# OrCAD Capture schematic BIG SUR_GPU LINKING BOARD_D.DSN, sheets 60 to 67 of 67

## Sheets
60 P62  P1V8 VR for PLX-1: size B
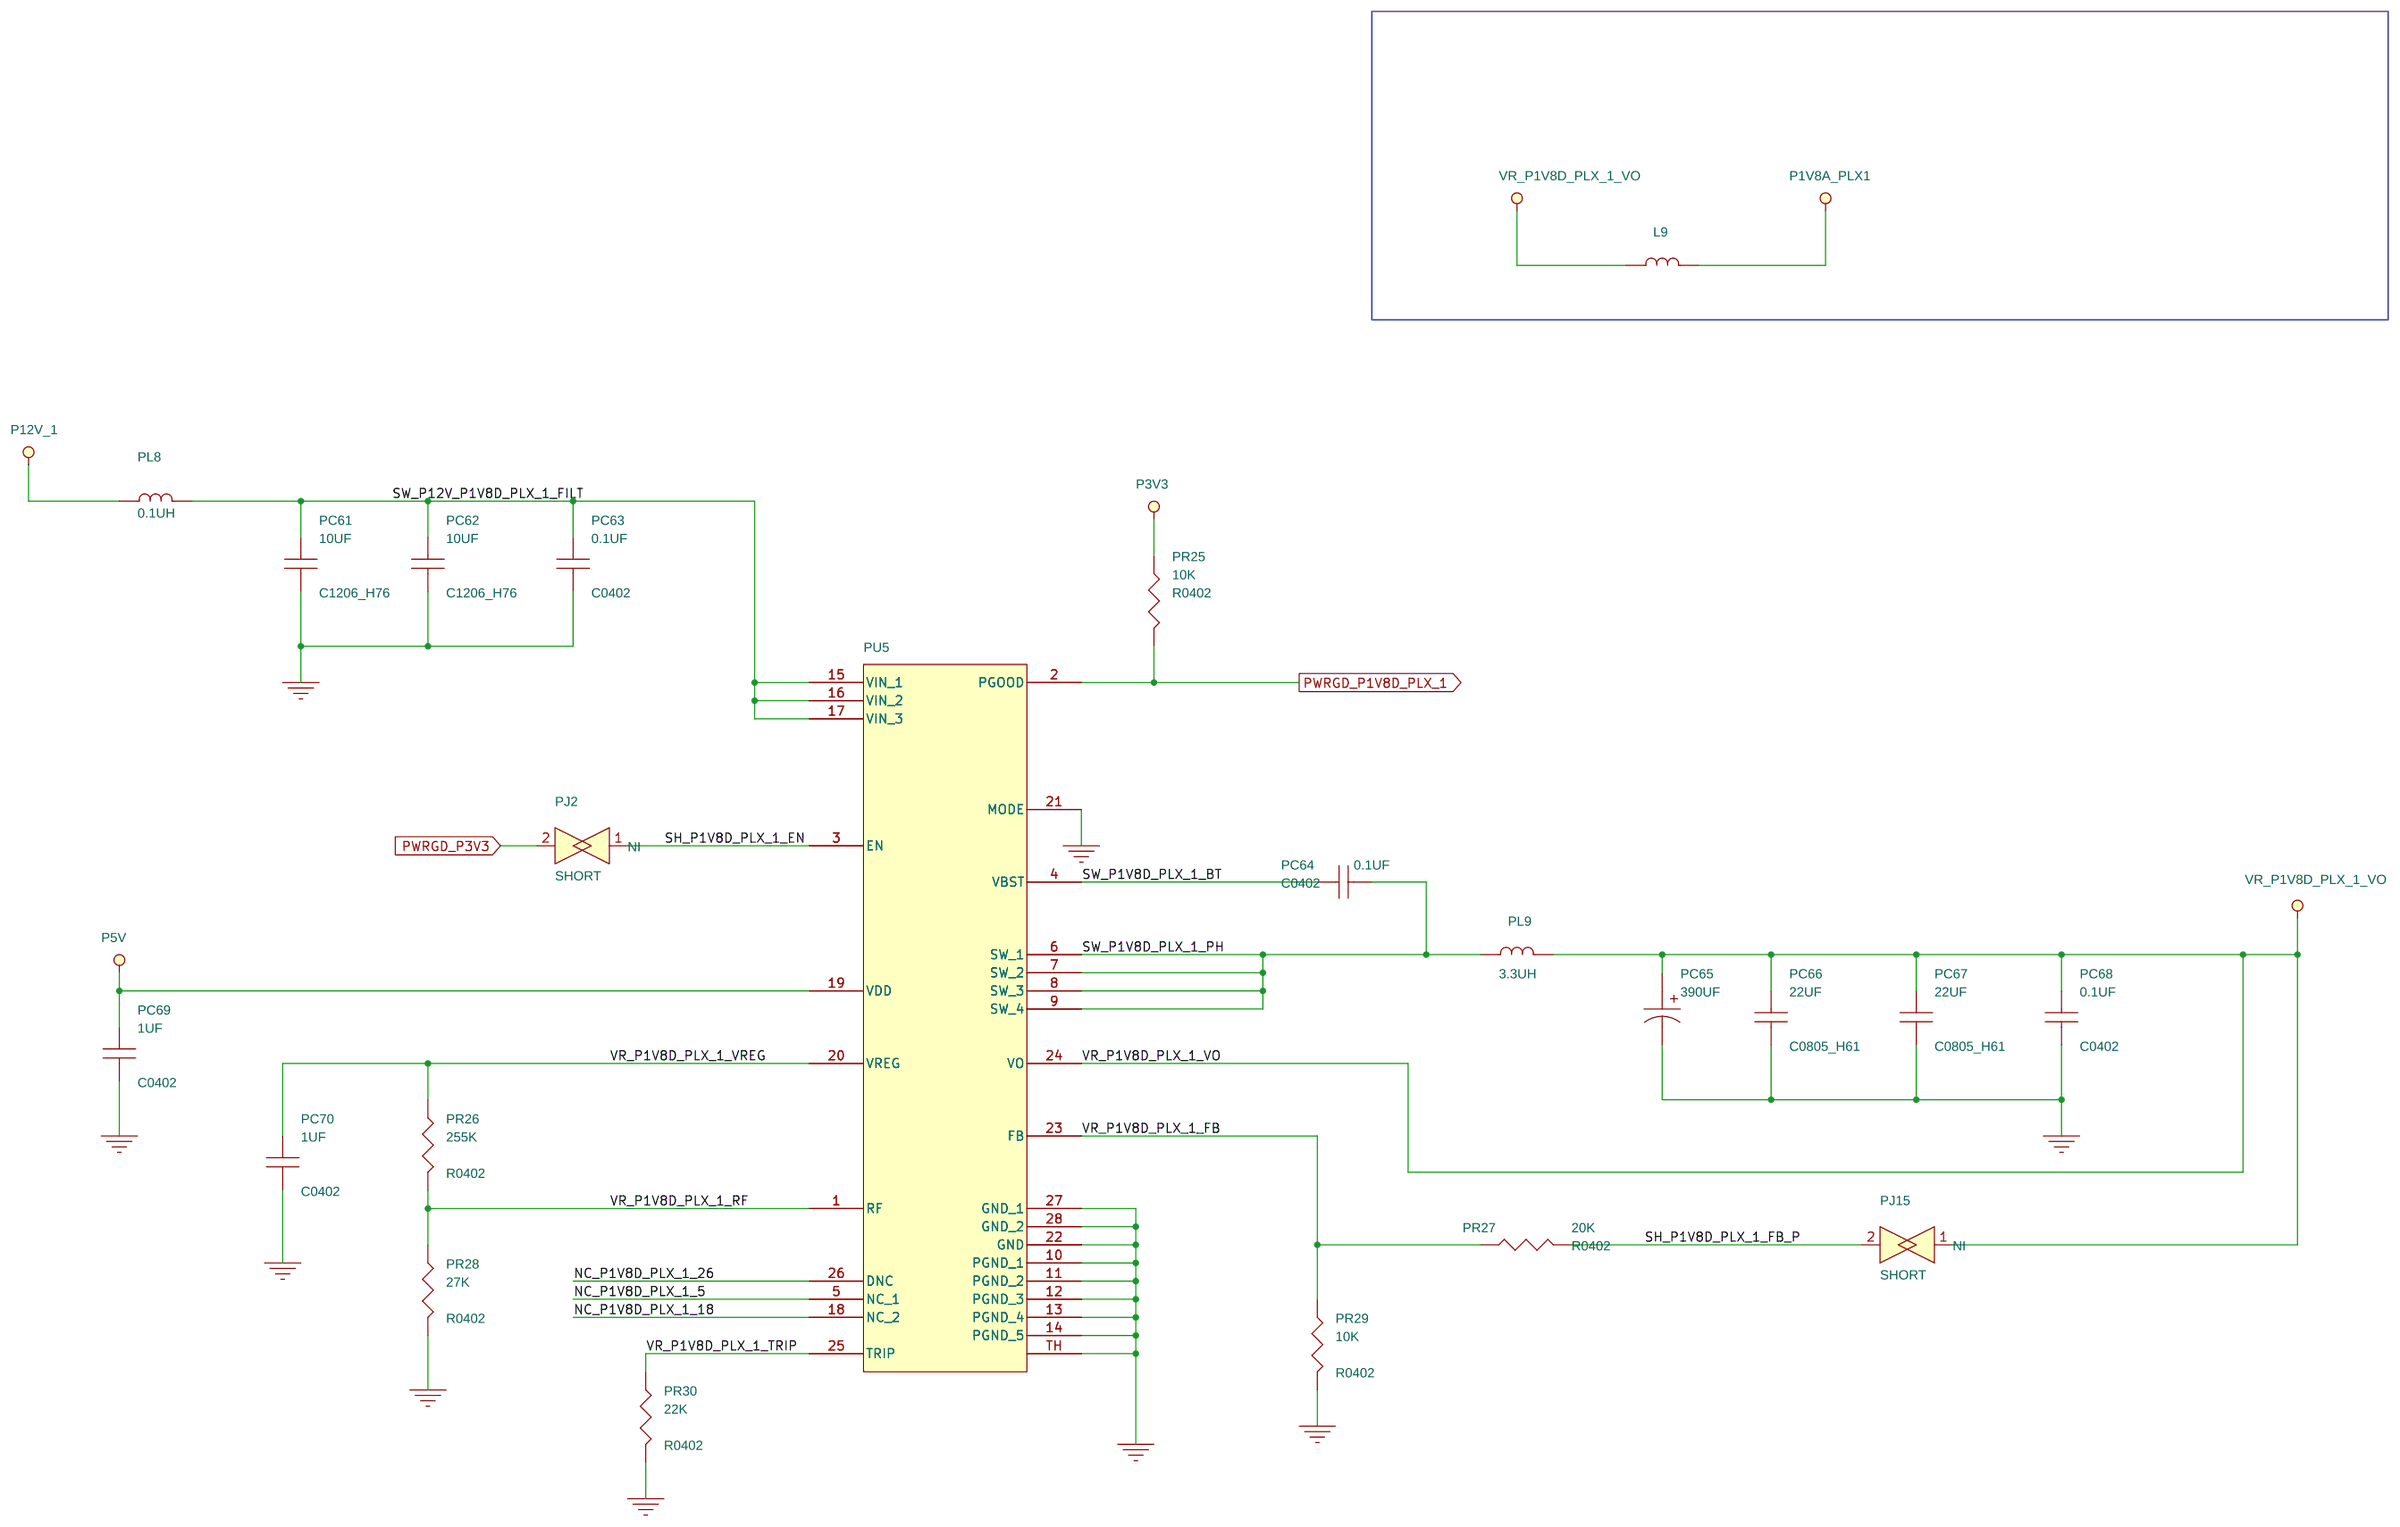
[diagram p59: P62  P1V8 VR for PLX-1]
61 P63  P1V8 VR for PLX-2: size B
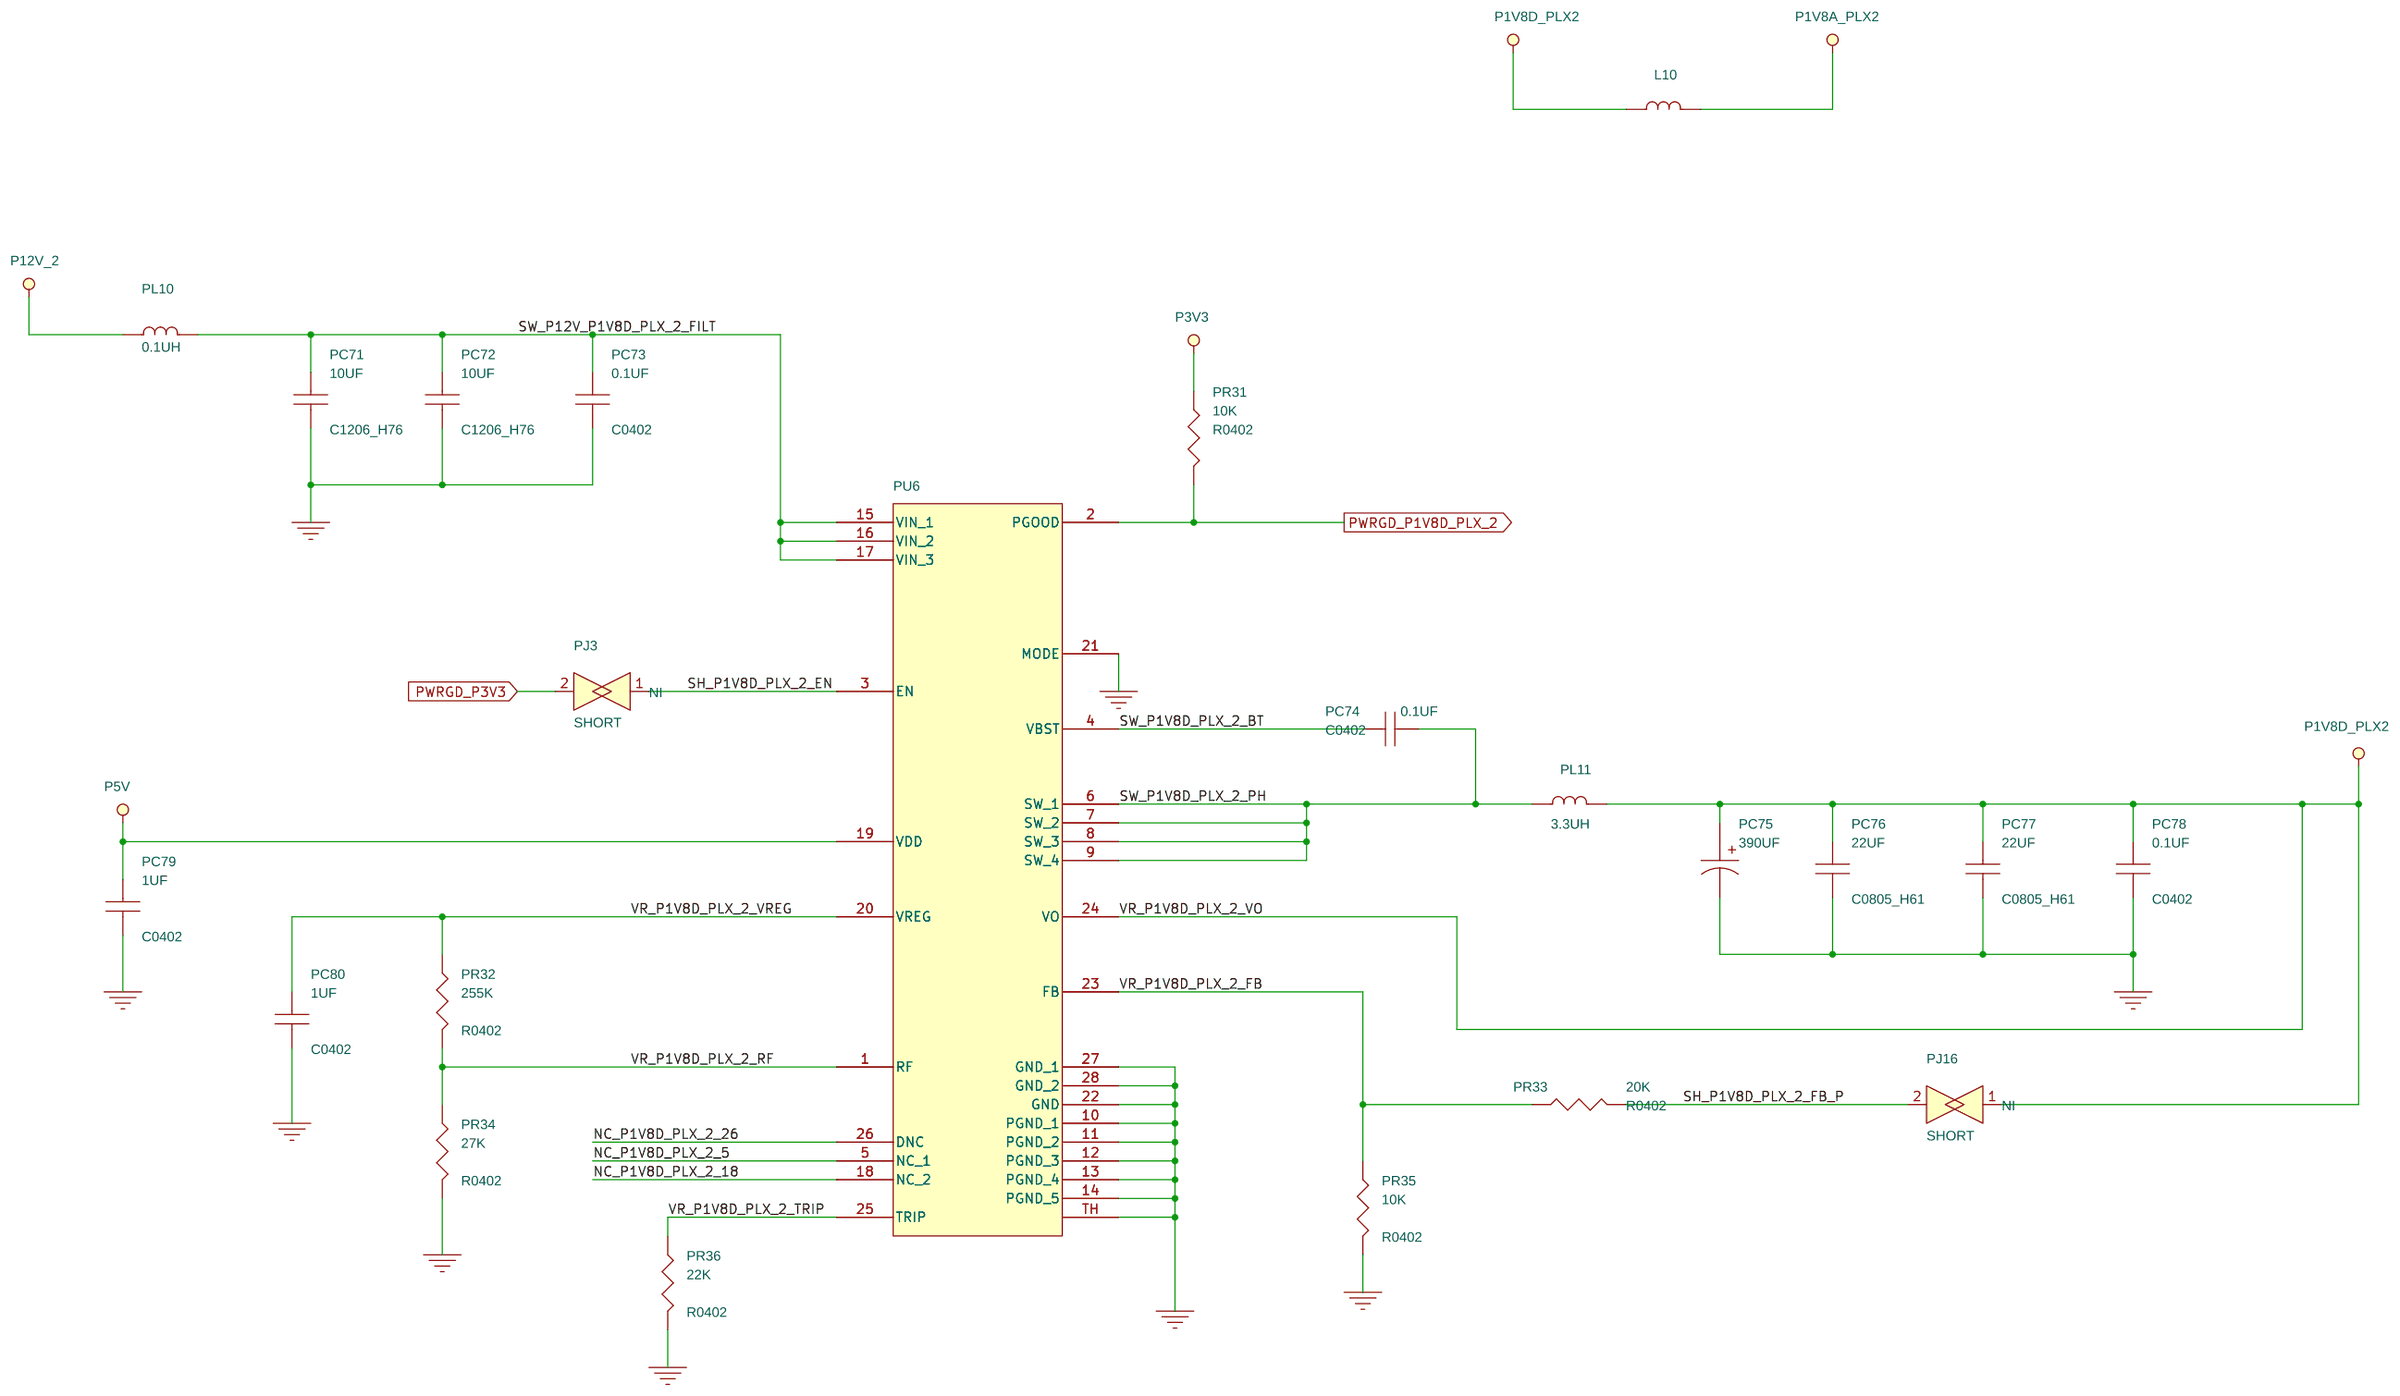
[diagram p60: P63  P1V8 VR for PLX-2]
62 P64  P0V9D VR for PLX-1: size A3
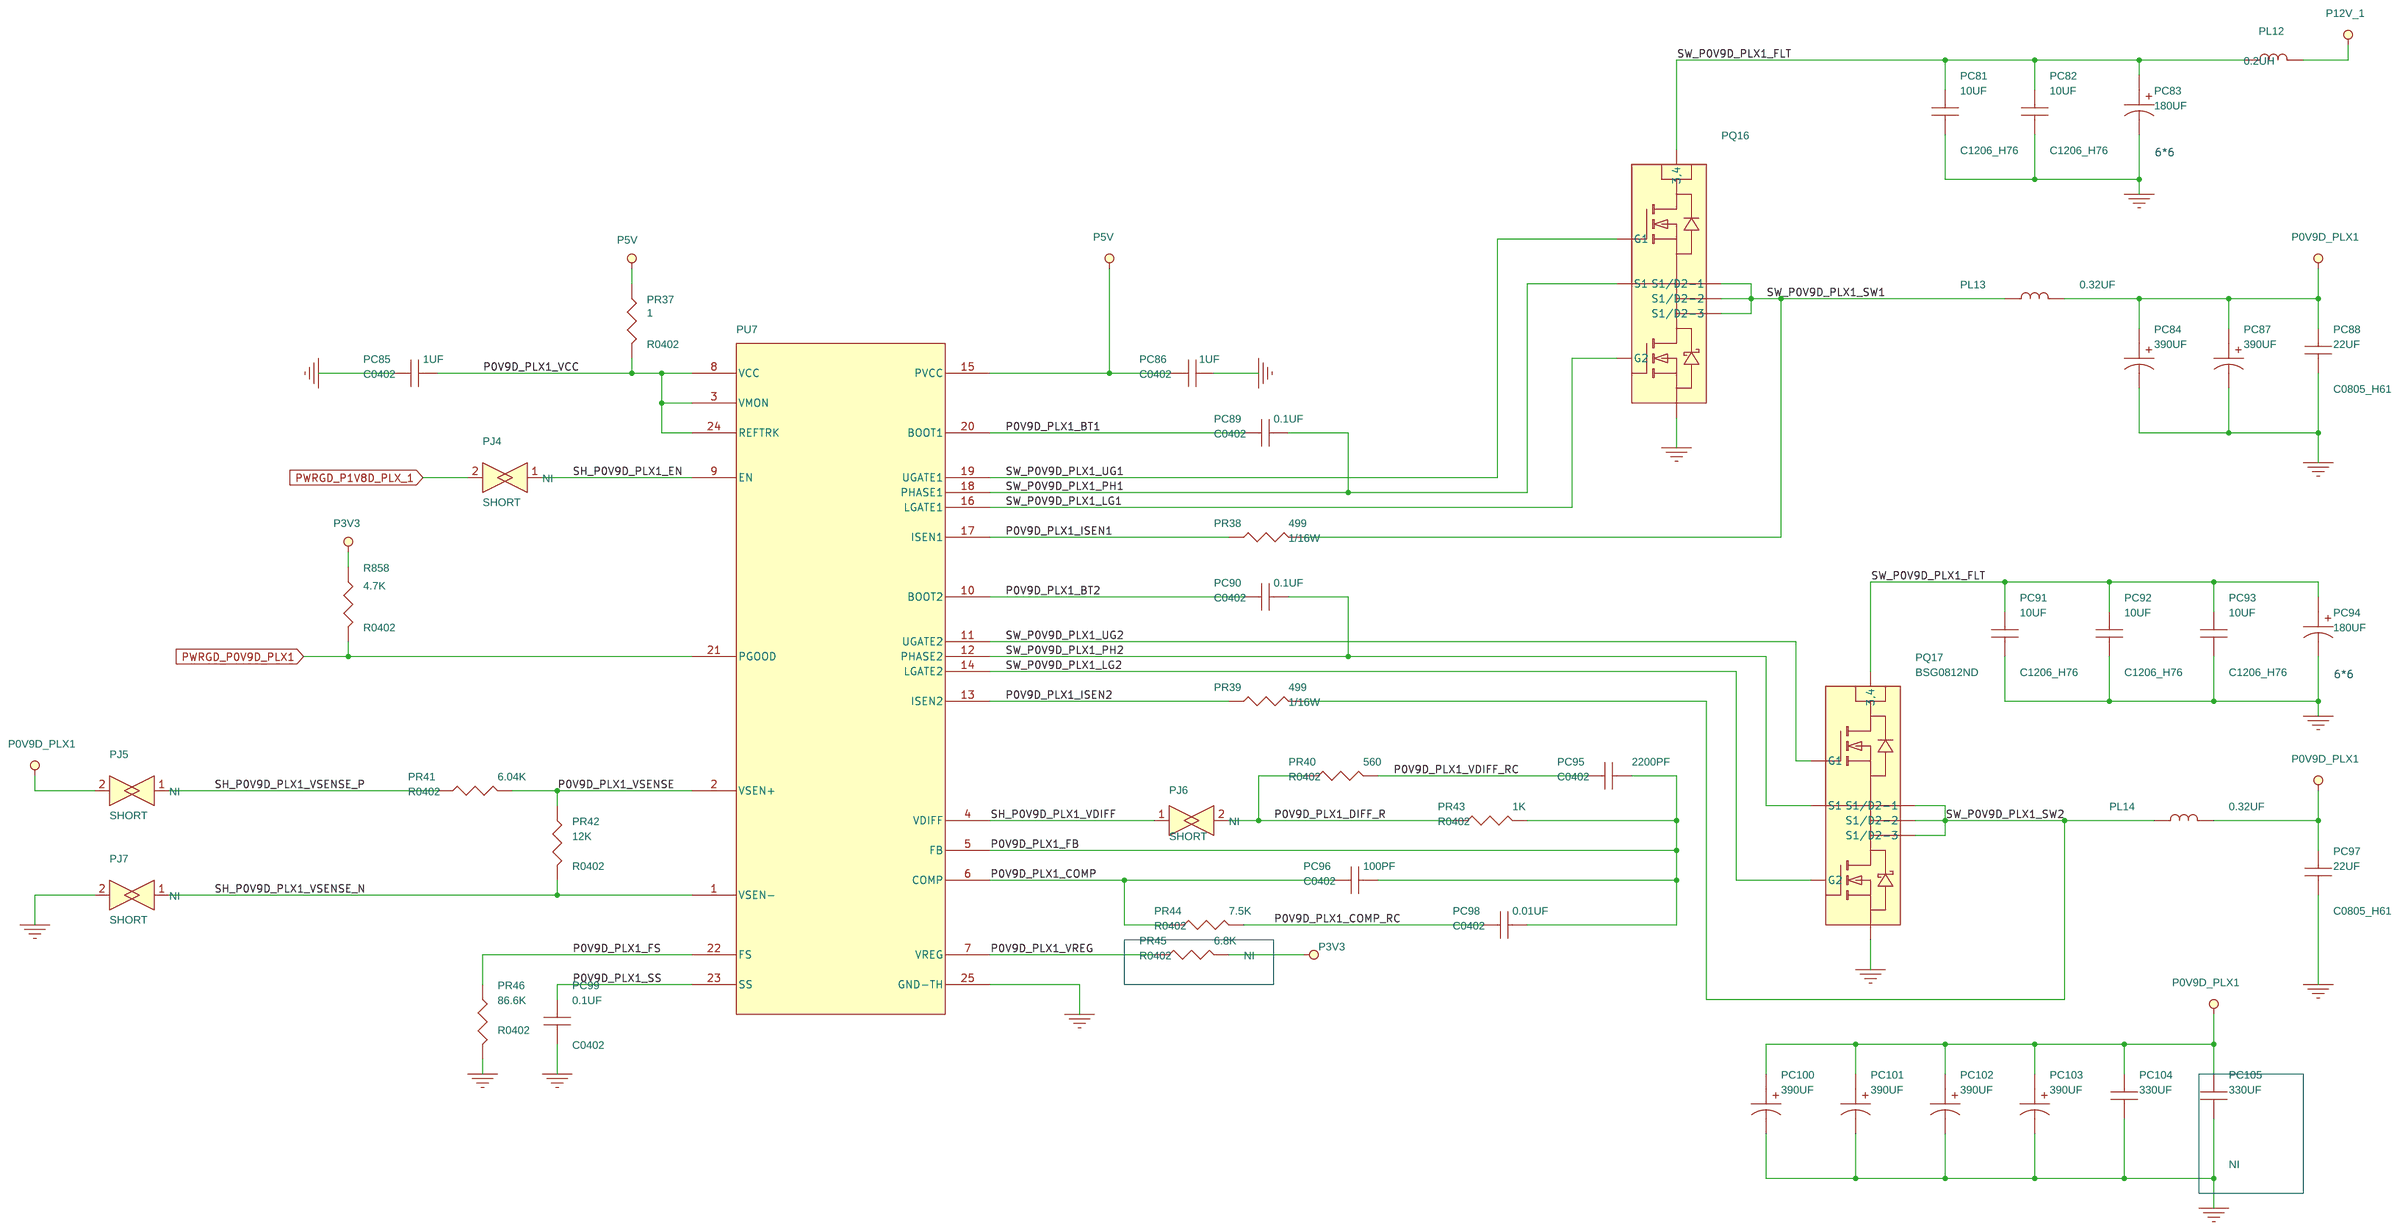
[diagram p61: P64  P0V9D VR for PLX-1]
63 P65  P0V9D VR for PLX-2: size A3
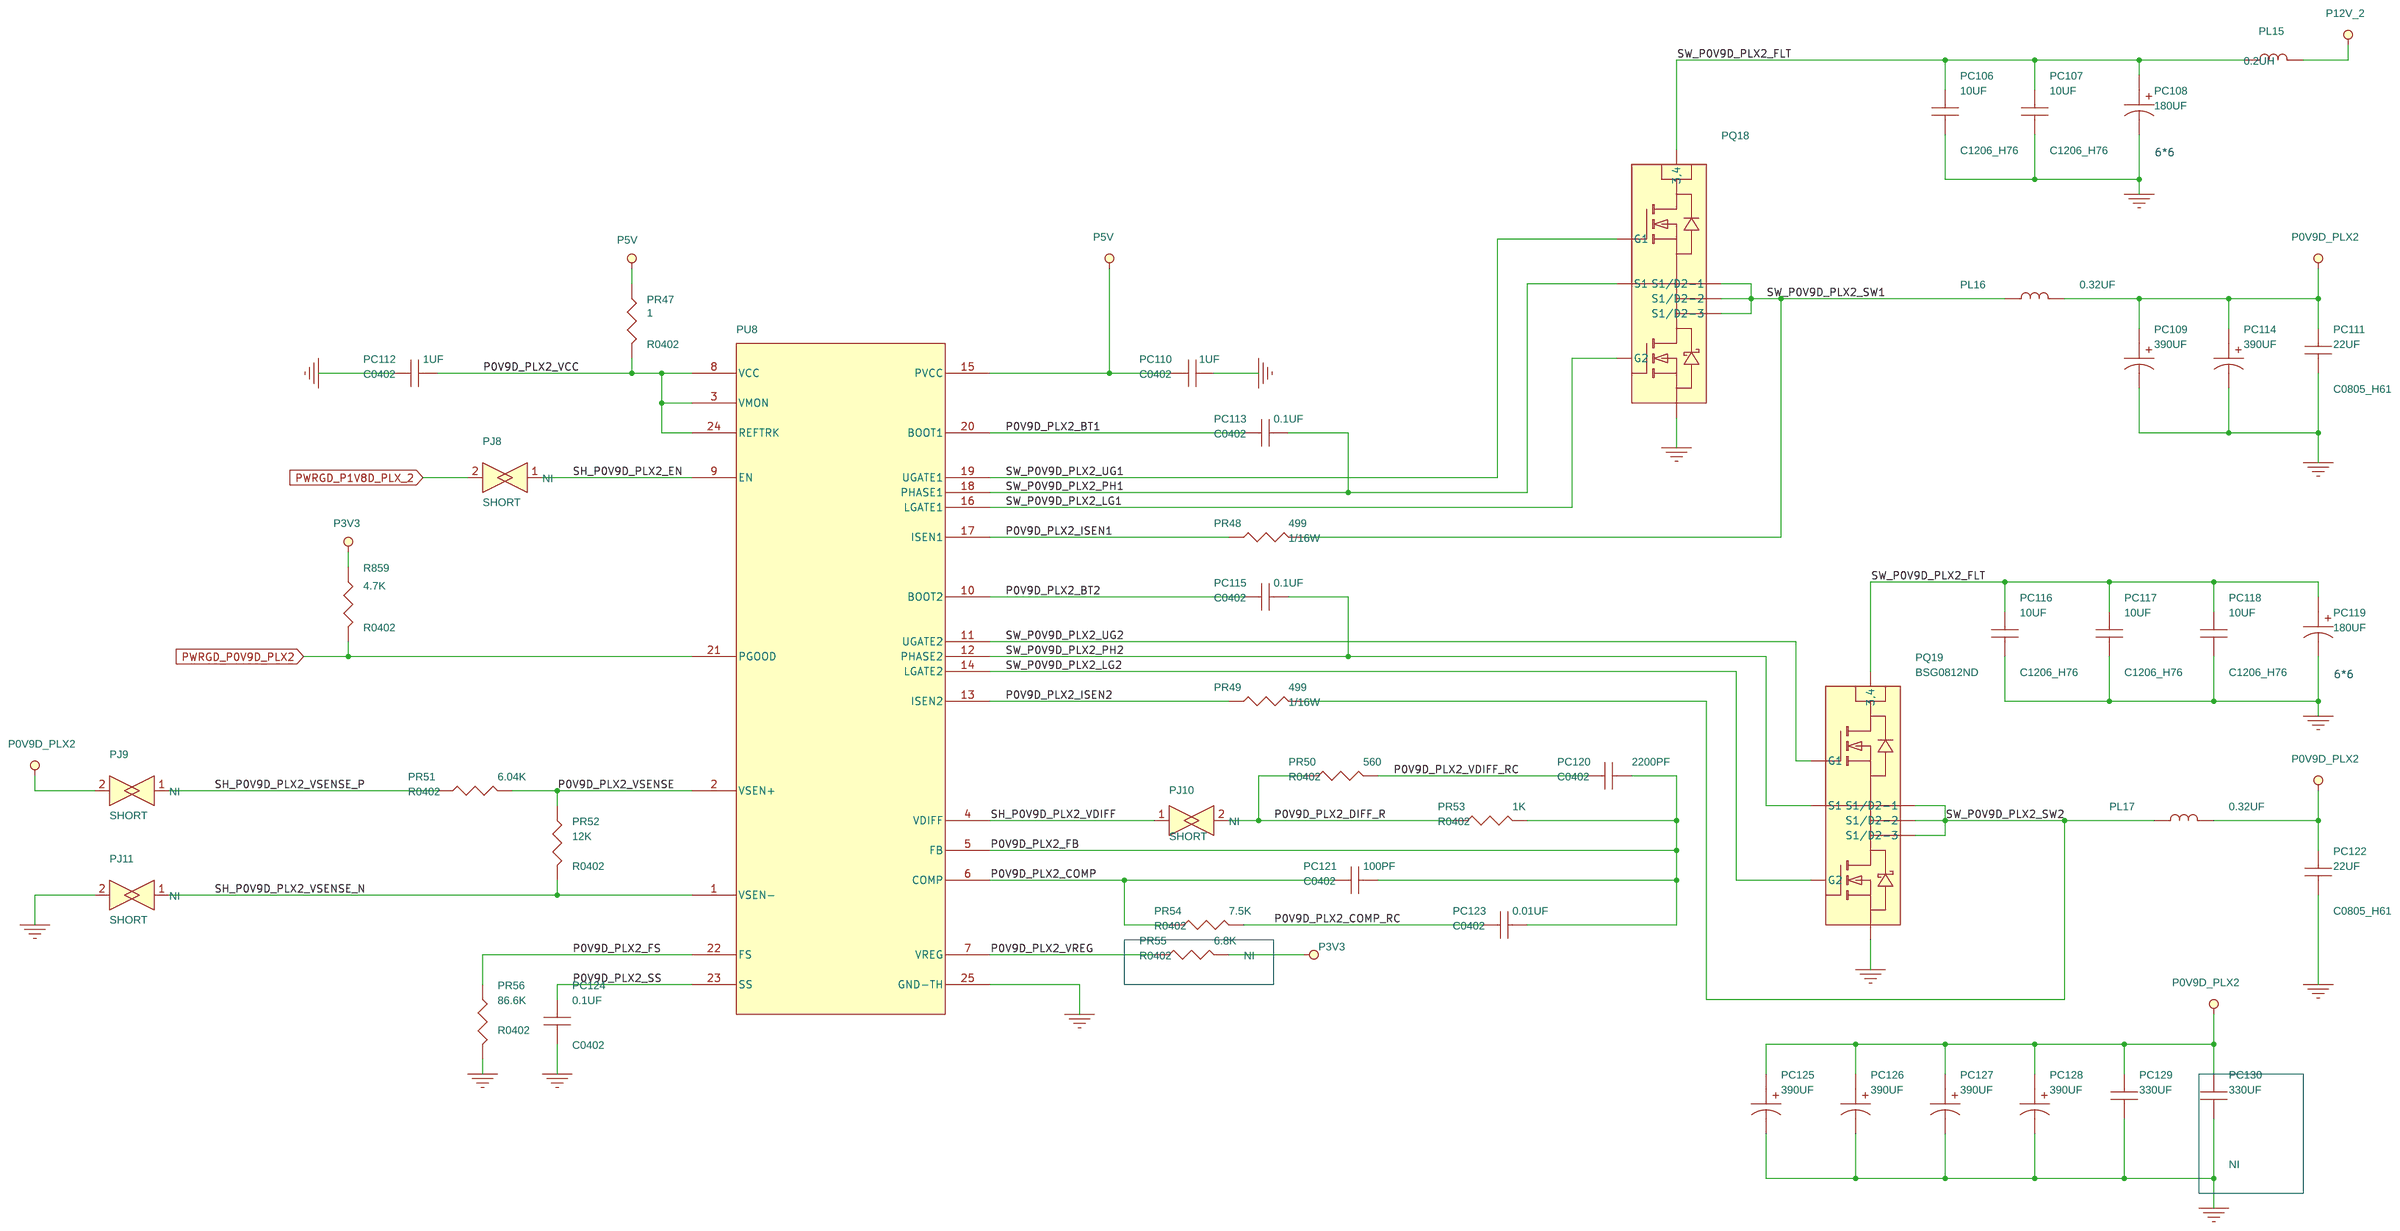
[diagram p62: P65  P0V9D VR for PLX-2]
64 P66  P0V9A VR for PLX-1: size A3
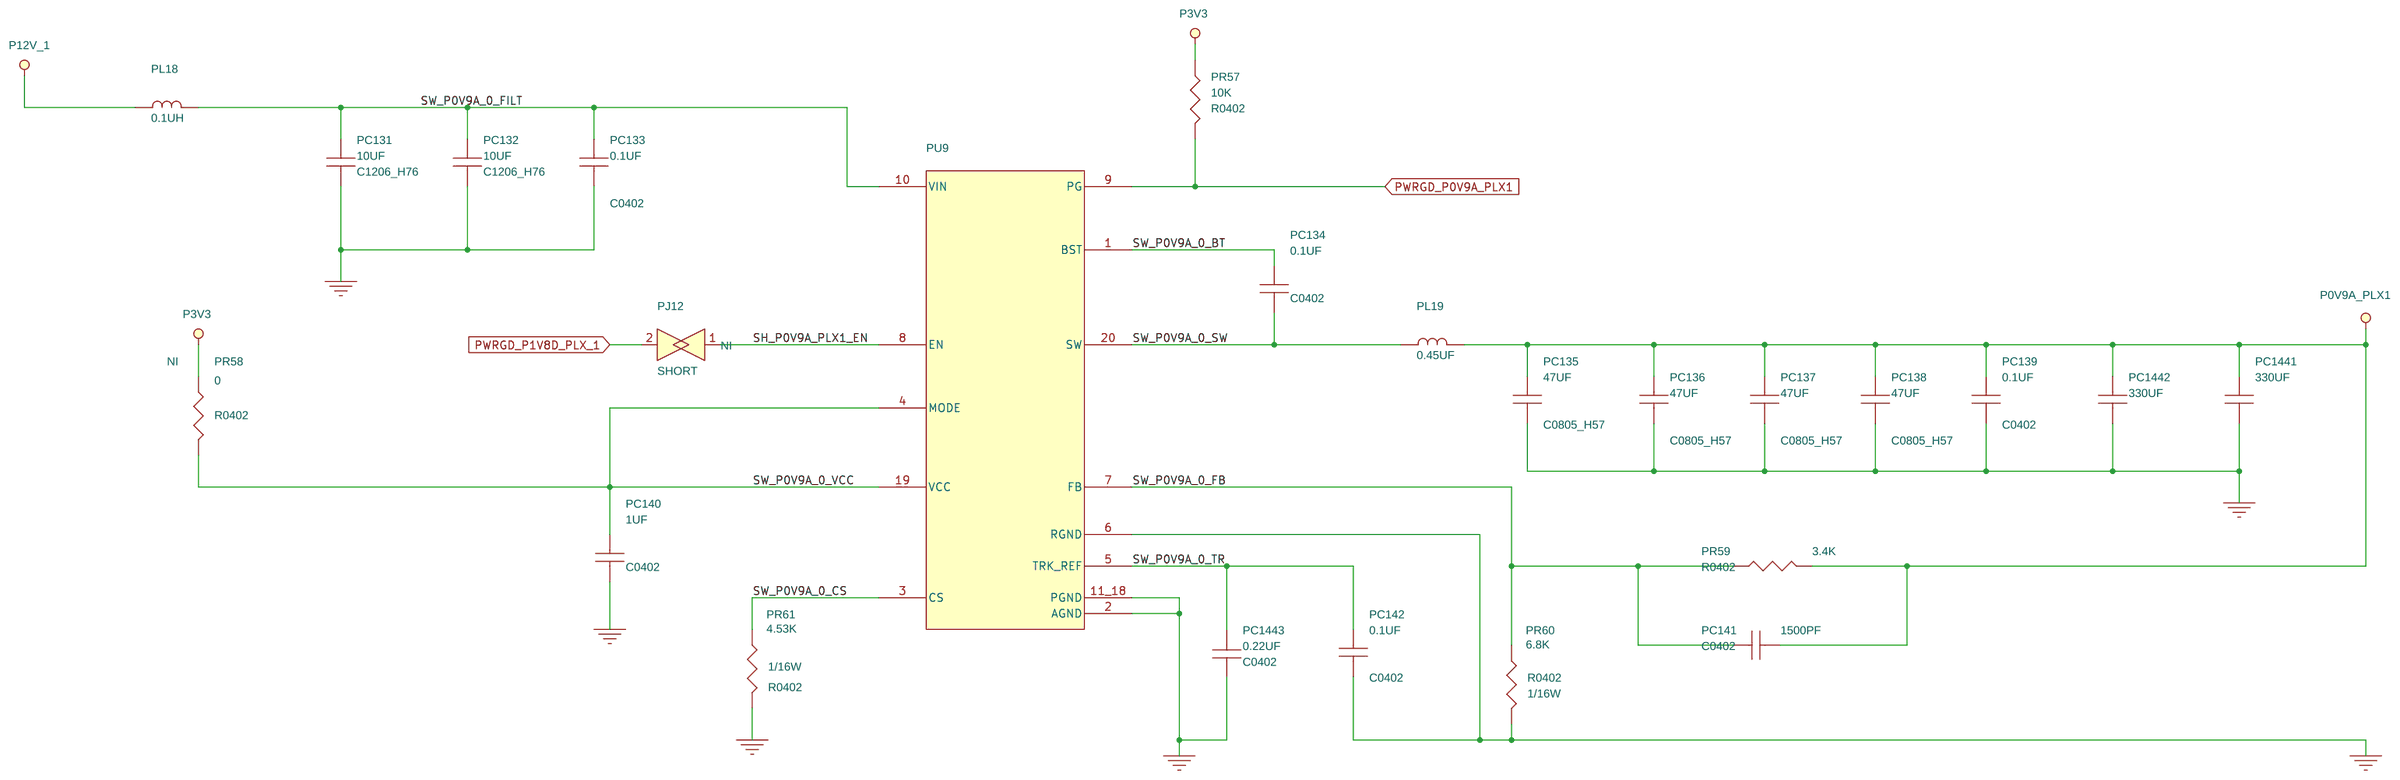
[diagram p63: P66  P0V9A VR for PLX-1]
65 P67  P0V9A VR for PLX-2: size A3
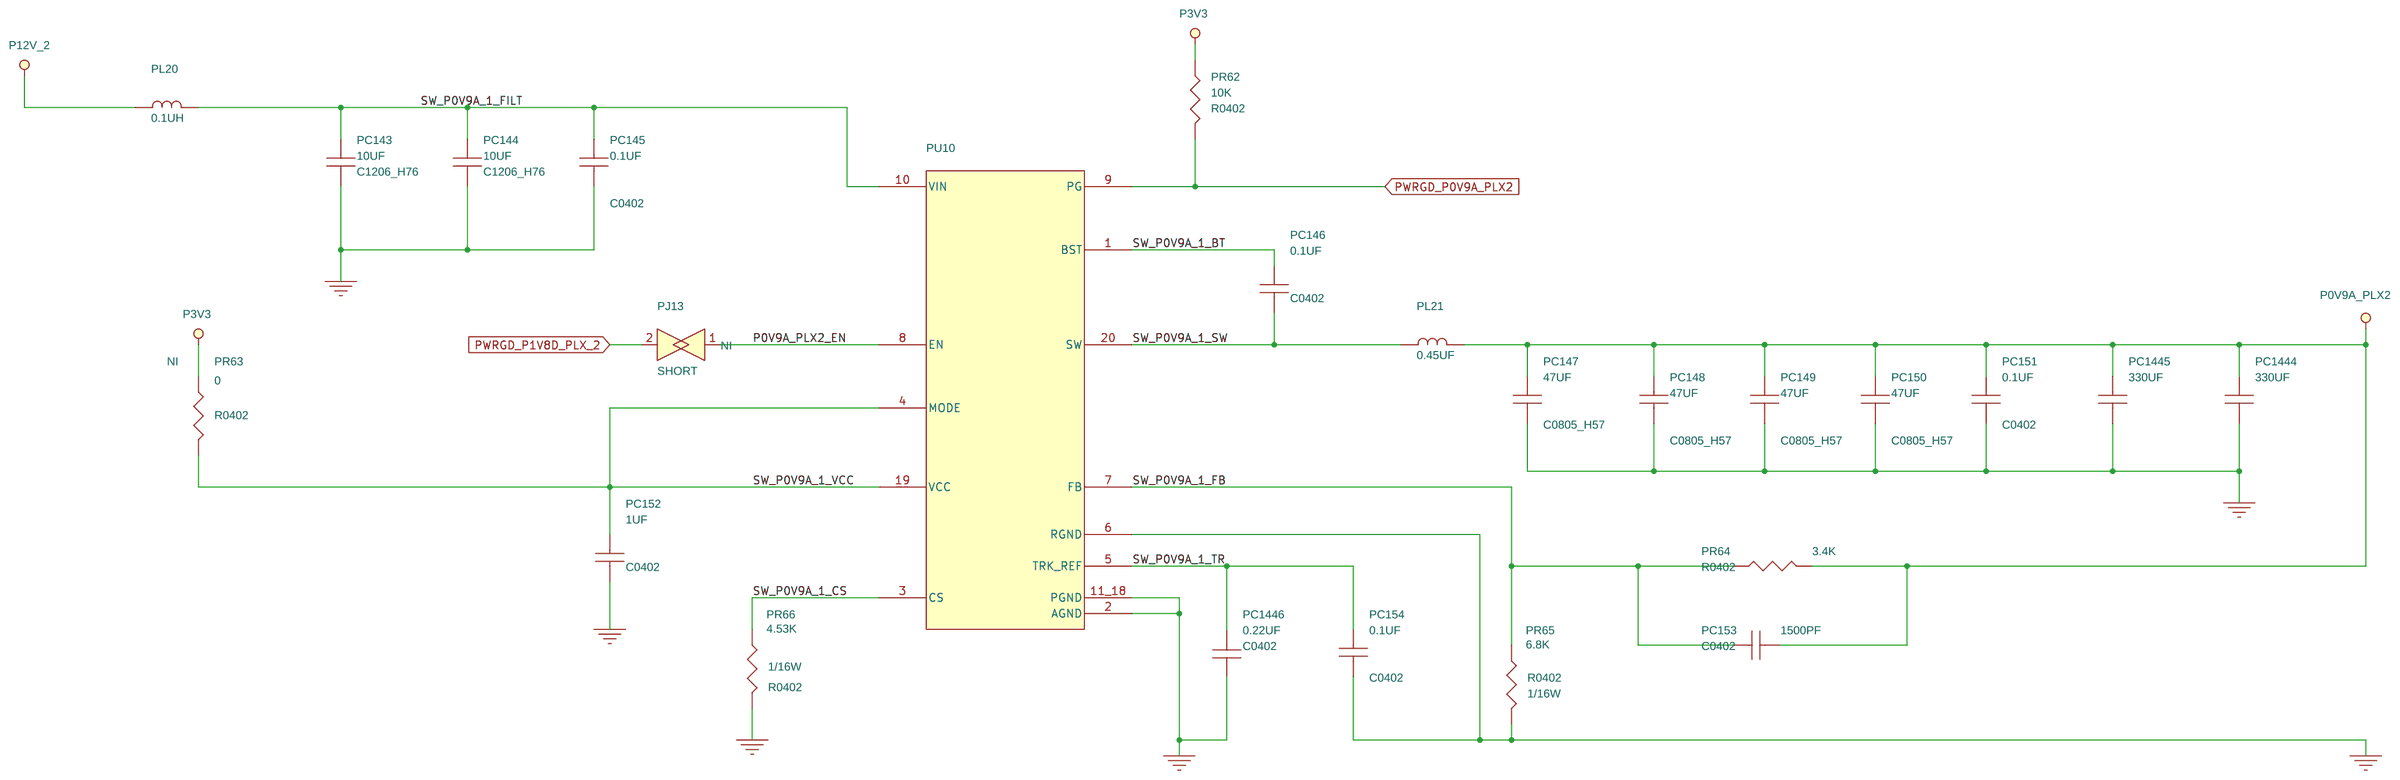
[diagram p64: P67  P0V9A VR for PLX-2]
66 P43  HDD B/P Power Connector: size B
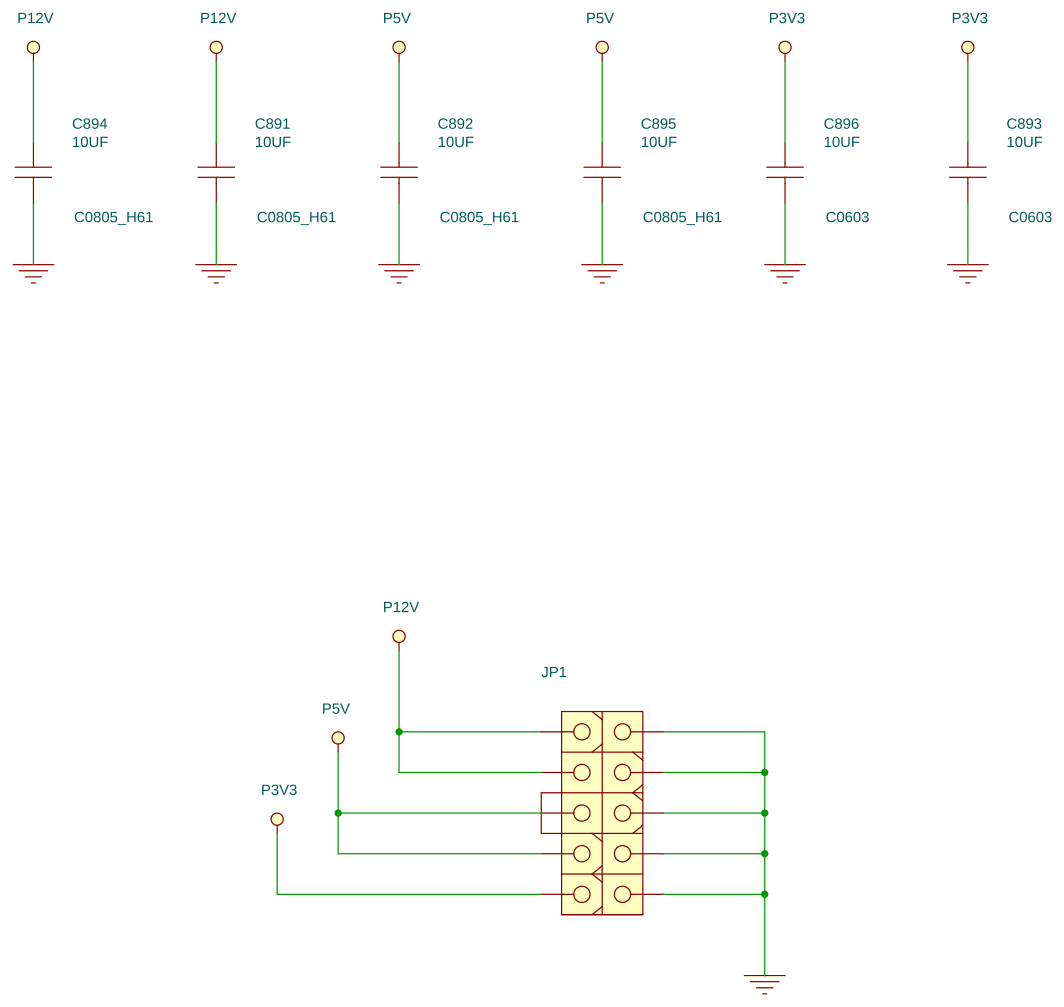
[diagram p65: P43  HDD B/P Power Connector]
67 P55  Power Control/GPU Throttle: size Custom
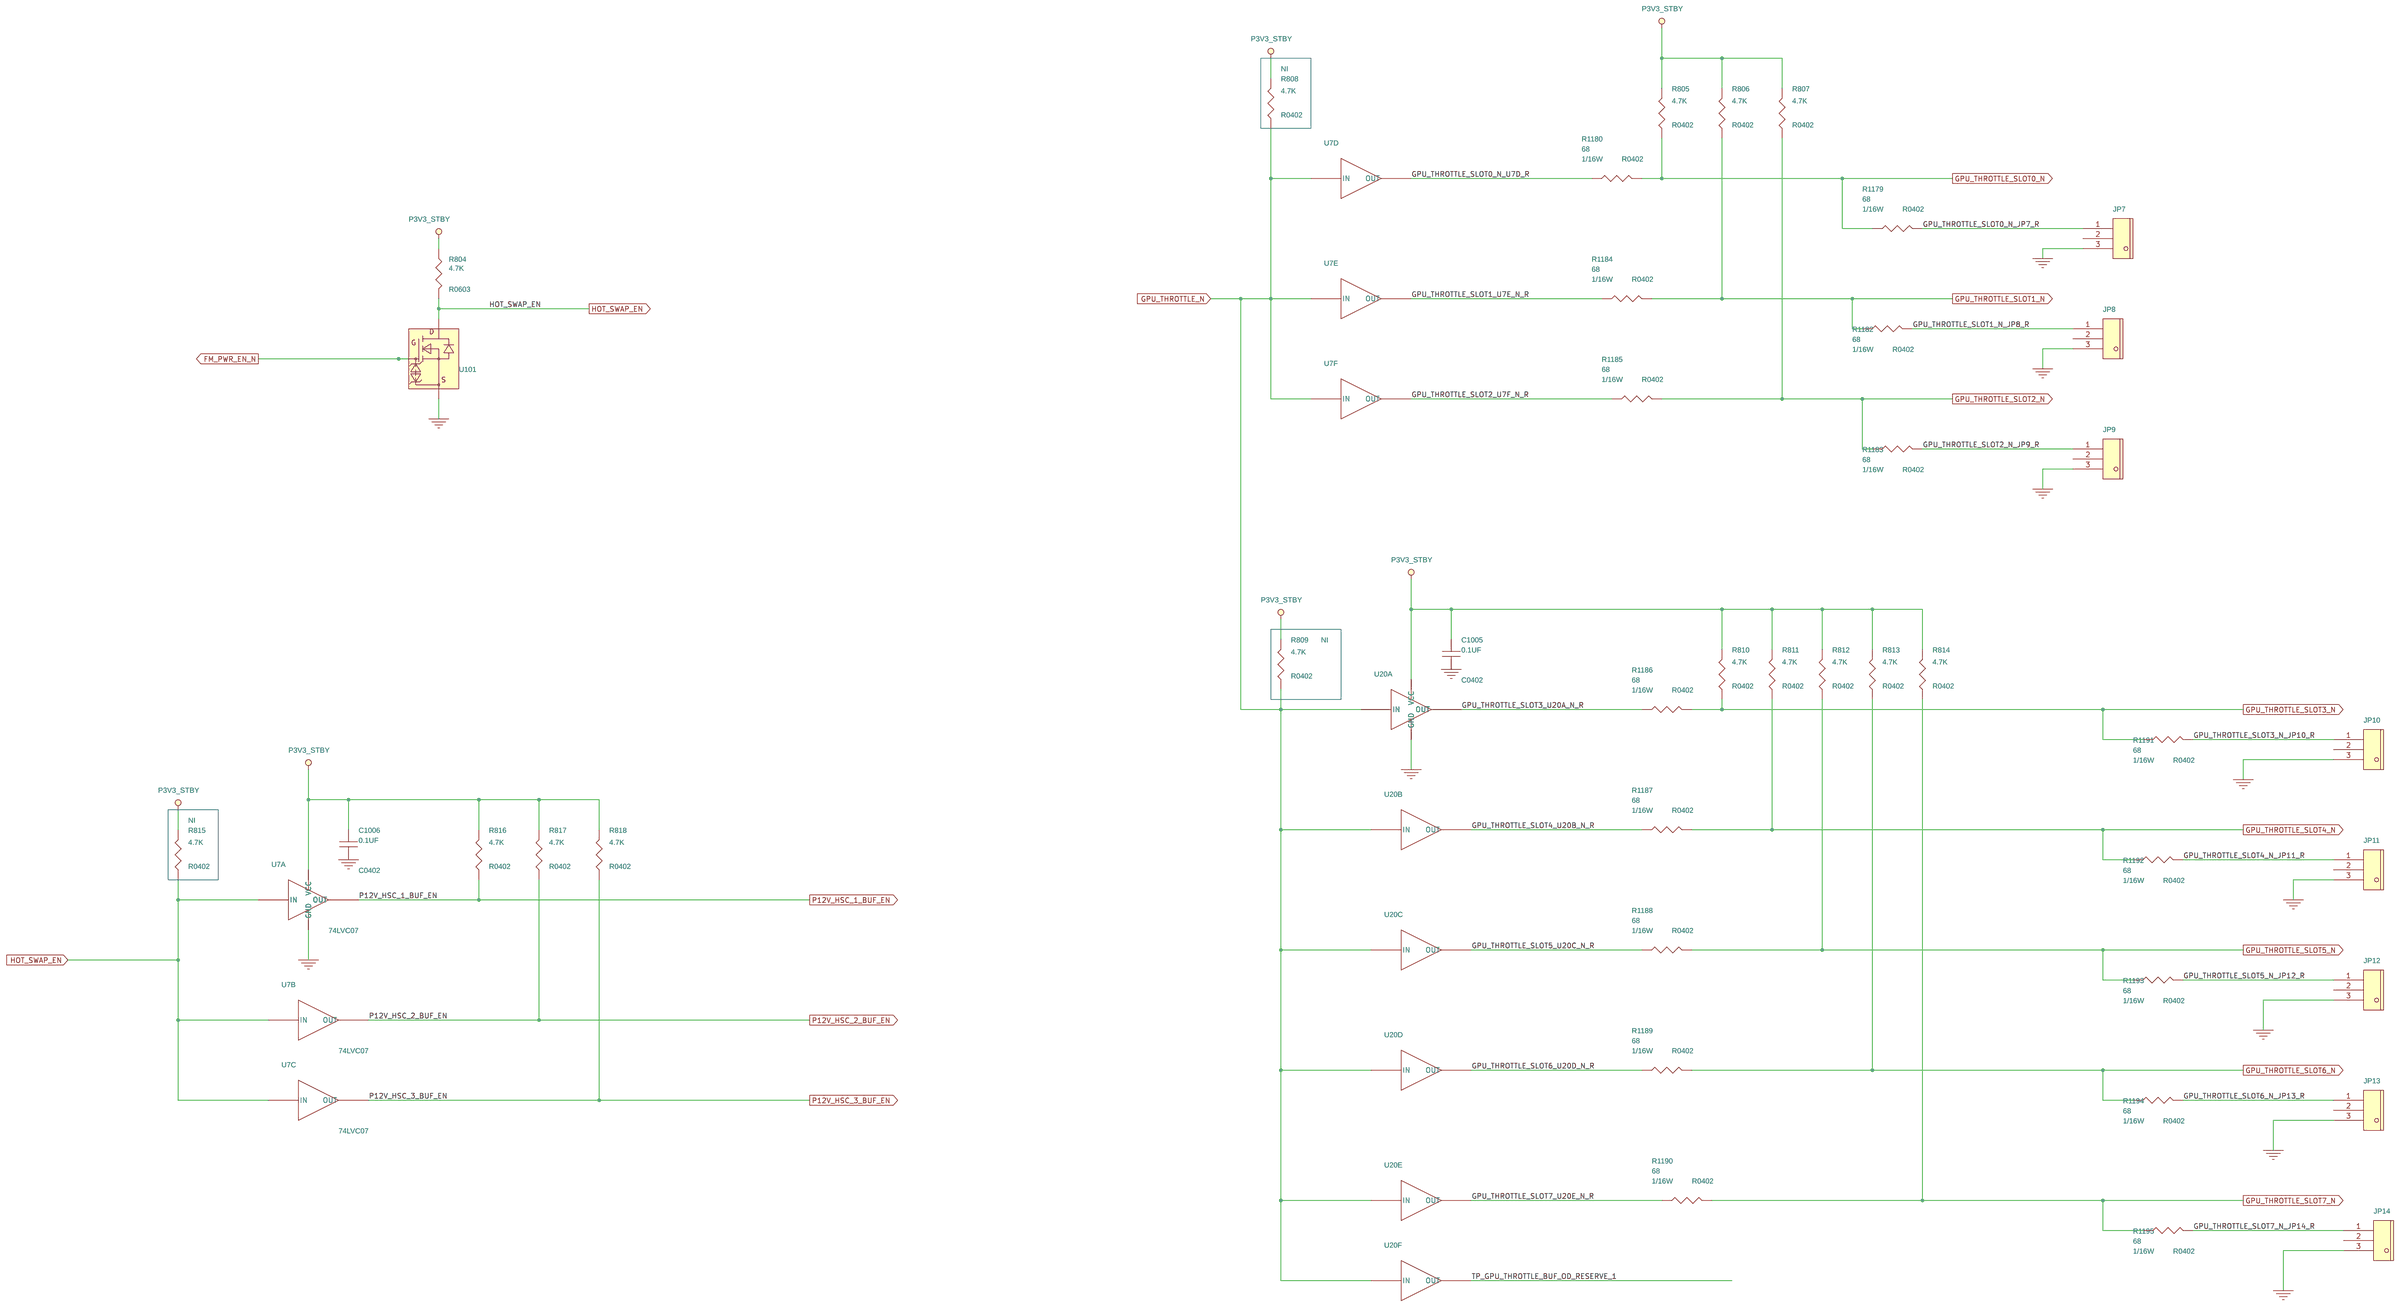
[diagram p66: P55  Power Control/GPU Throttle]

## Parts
sheet P43  HDD B/P Power Connector
C891  10UF  [C0805_H61]
C892  10UF  [C0805_H61]
C893  10UF  [C0603]
C894  10UF  [C0805_H61]
C895  10UF  [C0805_H61]
C896  10UF  [C0603]
JP1  CONN10  [CON_PWR2X5]
sheet P55  Power Control/GPU Throttle
C1005  0.1UF  [C0402]
C1006  0.1UF  [C0402]
JP7  CONN3_HF5503EP1  [HEADER1X3BHXB]
JP8  CONN3_HF5503EP1  [HEADER1X3BHXB]
JP9  CONN3_HF5503EP1  [HEADER1X3BHXB]
JP10  CONN3_HF5503EP1  [HEADER1X3BHXB]
JP11  CONN3_HF5503EP1  [HEADER1X3BHXB]
JP12  CONN3_HF5503EP1  [HEADER1X3BHXB]
JP13  CONN3_HF5503EP1  [HEADER1X3BHXB]
JP14  CONN3_HF5503EP1  [HEADER1X3BHXB]
R804  4.7K  [R0603]
R805  4.7K  [R0402]
R806  4.7K  [R0402]
R807  4.7K  [R0402]
R808  4.7K  [R0402]
R809  4.7K  [R0402]
R810  4.7K  [R0402]
R811  4.7K  [R0402]
R812  4.7K  [R0402]
R813  4.7K  [R0402]
R814  4.7K  [R0402]
R815  4.7K  [R0402]
R816  4.7K  [R0402]
R817  4.7K  [R0402]
R818  4.7K  [R0402]
R1179  68  [R0402]
R1180  68  [R0402]
R1182  68  [R0402]
R1183  68  [R0402]
R1184  68  [R0402]
R1185  68  [R0402]
R1186  68  [R0402]
R1187  68  [R0402]
R1188  68  [R0402]
R1189  68  [R0402]
R1190  68  [R0402]
R1191  68  [R0402]
R1192  68  [R0402]
R1193  68  [R0402]
R1194  68  [R0402]
R1195  68  [R0402]
U7  74LVC07  [TSSOP14]  (sections A,B,C,D,E,F)
U20  74LVC07  [TSSOP14]  (sections A,B,C,D,E,F)
U101  2N7002KW  [SOT323XB]
sheet P62  P1V8 VR for PLX-1
L9  MPZ2012S300A  [L0805]
PC61  10UF  [C1206_H76]
PC62  10UF  [C1206_H76]
PC63  0.1UF  [C0402]
PC64  0.1UF  [C0402]
PC65  390UF  [EC56_197_229S]
PC66  22UF  [C0805_H61]
PC67  22UF  [C0805_H61]
PC68  0.1UF  [C0402]
PC69  1UF  [C0402]
PC70  1UF  [C0402]
PJ2  SHORT  [SHORT_R0402_M]
PJ15  SHORT  [SHORT_R0402_M]
PL8  0.1UH  [L_MSI-400406]
PL9  3.3UH  [L_PCMB104TXB]
PR25  10K  [R0402]
PR26  255K  [R0402]
PR27  20K  [R0402]
PR28  27K  [R0402]
PR29  10K  [R0402]
PR30  22K  [R0402]
PU5  IC  [QFN28_THXK]
sheet P63  P1V8 VR for PLX-2
L10  MPZ2012S300A  [L0805]
PC71  10UF  [C1206_H76]
PC72  10UF  [C1206_H76]
PC73  0.1UF  [C0402]
PC74  0.1UF  [C0402]
PC75  390UF  [EC56_197_229S]
PC76  22UF  [C0805_H61]
PC77  22UF  [C0805_H61]
PC78  0.1UF  [C0402]
PC79  1UF  [C0402]
PC80  1UF  [C0402]
PJ3  SHORT  [SHORT_R0402_M]
PJ16  SHORT  [SHORT_R0402_M]
PL10  0.1UH  [L_MSI-400406]
PL11  3.3UH  [L_PCMB104TXB]
PR31  10K  [R0402]
PR32  255K  [R0402]
PR33  20K  [R0402]
PR34  27K  [R0402]
PR35  10K  [R0402]
PR36  22K  [R0402]
PU6  IC  [QFN28_THXK]
sheet P64  P0V9D VR for PLX-1
PC81  10UF  [C1206_H76]
PC82  10UF  [C1206_H76]
PC83  180UF  [EC83_248_232S]
PC84  390UF  [EC56_197_229S]
PC85  1UF  [C0402]
PC86  1UF  [C0402]
PC87  390UF  [EC56_197_229S]
PC88  22UF  [C0805_H61]
PC89  0.1UF  [C0402]
PC90  0.1UF  [C0402]
PC91  10UF  [C1206_H76]
PC92  10UF  [C1206_H76]
PC93  10UF  [C1206_H76]
PC94  180UF  [EC83_248_232S]
PC95  2200PF  [C0402]
PC96  100PF  [C0402]
PC97  22UF  [C0805_H61]
PC98  0.01UF  [C0402]
PC99  0.1UF  [C0402]
PC100  390UF  [EC56_197_229S]
PC101  390UF  [EC56_197_229S]
PC102  390UF  [EC56_197_229S]
PC103  390UF  [EC56_197_229S]
PC104  330UF  [TAJ_SX]
PC105  330UF  [TAJ_SX]
PJ4  SHORT  [SHORT_R0402_M]
PJ5  SHORT  [SHORT_R0402_M]
PJ6  SHORT  [SHORT_R0603]
PJ7  SHORT  [SHORT_R0402_M]
PL12  0.2UH  [L_MSI-600608]
PL13  0.32UF  [L_HCB141390]
PL14  0.32UF  [L_HCB141390]
PQ16  BSG0812ND  [PG-TISON8-4]
PQ17  BSG0812ND  [PG-TISON8-4]
PR37  1  [R0402]
PR38  499  [R0402]
PR39  499  [R0402]
PR40  560  [R0402]
PR41  6.04K  [R0402]
PR42  12K  [R0402]
PR43  1K  [R0402]
PR44  7.5K  [R0402]
PR45  6.8K  [R0402]
PR46  86.6K  [R0402]
PU7  ISL8121IRZ-T  [QFN24_TH]
R858  4.7K  [R0402]
sheet P65  P0V9D VR for PLX-2
PC106  10UF  [C1206_H76]
PC107  10UF  [C1206_H76]
PC108  180UF  [EC83_248_232S]
PC109  390UF  [EC56_197_229S]
PC110  1UF  [C0402]
PC111  22UF  [C0805_H61]
PC112  1UF  [C0402]
PC113  0.1UF  [C0402]
PC114  390UF  [EC56_197_229S]
PC115  0.1UF  [C0402]
PC116  10UF  [C1206_H76]
PC117  10UF  [C1206_H76]
PC118  10UF  [C1206_H76]
PC119  180UF  [EC83_248_232S]
PC120  2200PF  [C0402]
PC121  100PF  [C0402]
PC122  22UF  [C0805_H61]
PC123  0.01UF  [C0402]
PC124  0.1UF  [C0402]
PC125  390UF  [EC56_197_229S]
PC126  390UF  [EC56_197_229S]
PC127  390UF  [EC56_197_229S]
PC128  390UF  [EC56_197_229S]
PC129  330UF  [TAJ_SX]
PC130  330UF  [TAJ_SX]
PJ8  SHORT  [SHORT_R0402_M]
PJ9  SHORT  [SHORT_R0402_M]
PJ10  SHORT  [SHORT_R0603]
PJ11  SHORT  [SHORT_R0402_M]
PL15  0.2UH  [L_MSI-600608]
PL16  0.32UF  [L_HCB141390]
PL17  0.32UF  [L_HCB141390]
PQ18  BSG0812ND  [PG-TISON8-4]
PQ19  BSG0812ND  [PG-TISON8-4]
PR47  1  [R0402]
PR48  499  [R0402]
PR49  499  [R0402]
PR50  560  [R0402]
PR51  6.04K  [R0402]
PR52  12K  [R0402]
PR53  1K  [R0402]
PR54  7.5K  [R0402]
PR55  6.8K  [R0402]
PR56  86.6K  [R0402]
PU8  IC  [QFN24_TH]
R859  4.7K  [R0402]
sheet P66  P0V9A VR for PLX-1
PC131  10UF  [C1206_H76]
PC132  10UF  [C1206_H76]
PC133  0.1UF  [C0402]
PC134  0.1UF  [C0402]
PC135  47UF  [C0805_H57]
PC136  47UF  [C0805_H57]
PC137  47UF  [C0805_H57]
PC138  47UF  [C0805_H57]
PC139  0.1UF  [C0402]
PC140  1UF  [C0402]
PC141  1500PF  [C0402]
PC142  0.1UF  [C0402]
PC1441  330UF  [TAJ_SX]
PC1442  330UF  [TAJ_SX]
PC1443  0.22UF  [C0402]
PJ12  SHORT  [SHORT_R0402_M]
PL18  0.1UH  [L_MSI-400406]
PL19  0.45UF  [L_PCMB104TXB]
PR57  10K  [R0402]
PR58  0  [R0402]
PR59  3.4K  [R0402]
PR60  6.8K  [R0402]
PR61  4.53K  [R0402]
PU9  IC  [QFN20_3X4]
sheet P67  P0V9A VR for PLX-2
PC143  10UF  [C1206_H76]
PC144  10UF  [C1206_H76]
PC145  0.1UF  [C0402]
PC146  0.1UF  [C0402]
PC147  47UF  [C0805_H57]
PC148  47UF  [C0805_H57]
PC149  47UF  [C0805_H57]
PC150  47UF  [C0805_H57]
PC151  0.1UF  [C0402]
PC152  1UF  [C0402]
PC153  1500PF  [C0402]
PC154  0.1UF  [C0402]
PC1444  330UF  [TAJ_SX]
PC1445  330UF  [TAJ_SX]
PC1446  0.22UF  [C0402]
PJ13  SHORT  [SHORT_R0402_M]
PL20  0.1UH  [L_MSI-400406]
PL21  0.45UF  [L_PCMB104TXB]
PR62  10K  [R0402]
PR63  0  [R0402]
PR64  3.4K  [R0402]
PR65  6.8K  [R0402]
PR66  4.53K  [R0402]
PU10  IC  [QFN20_3X4]

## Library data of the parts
C891 C892 C894 C895 PC66 PC67 PC76 PC77 PC88 PC97 PC111 PC122 PC135-PC138 = CAP_NP: Part_Type: *LF_C0805
C893 C896 = CAP_NP: Part_Type: *LF_C0603
JP1 = CONN10_HM3505E: Part_Type: *LF_Connector
C1005 C1006 PC63 PC64 PC68-PC70 PC73 PC74 PC78-PC80 PC85 PC86 PC89 PC90 PC95 PC96 PC98 PC99 PC110 PC112 PC113 PC115 PC120 PC121 PC123 PC124 PC141 PC1443 = CAP_NP: Part_Type: *LF_C0402
JP7-JP14 = CONN3_HF5503EP1: Part_Type: *LF_Connector
R804 = R: Part_Type: *LF_Resistor; WATTAGE: 1/10W
PR25-PR44 PR46-PR54 PR56 PR57 PR59-PR61 R805-R807 R810-R814 R816-R818 R858 R859 R1179 R1180 R1182-R1195 = R: Part_Type: *LF_Resistor; WATTAGE: 1/16W
PR45 PR55 PR58 R808 R809 R815 = R: Not_insert: NI; Part_Type: *LF_Resistor; WATTAGE: 1/16W
U7 U20 = 74LVC07: Part_Type: Chipset
U101 = MOSFET_NCH_GDS_ESD_PROTECTED: Part_Type: *LF_Semiconductor
L9 L10 PL8-PL19 = L: Part_Type: *LF_Inductor
PC61 PC62 PC71 PC72 PC81 PC82 PC91-PC93 PC106 PC107 PC116-PC118 PC131 PC132 = CAP_NP: Part_Type: *LF_C1206
PC65 PC75 PC83 PC84 PC87 PC94 PC100-PC103 PC108 PC109 PC114 PC119 PC125-PC128 = CAPACITOR_POL: Part_Type: *LF_C_ELEC_SMD
PJ2-PJ13 PJ15 PJ16 = JUMPER-2_1: Not_insert: NI; Part_Type: Mech
PU5 PU6 = SN1401043RVER: Part_Type: *LF_Chipset
PC104 PC129 PC1441 PC1442 = CAP_NP: Part_Type: *LF_C_POSCAP
PC105 PC130 = CAP_NP: Not_insert: NI; Part_Type: *LF_C_POSCAP
PQ16-PQ19 = MOSFET_NCH_DUAL_1D1S: Part_Type: *LF_Semiconductor
PU7 PU8 = ISL8121IRZT: Part_Type: *LF_Chipset
PC133 PC134 PC139 PC140 PC142 = CAP_NP_0: Part_Type: *LF_C0402
PU9 = MPQ8633AGL: Part_Type: *LF_Chipset
PC143 PC144 = CAP_NP: Lifecycle: Comp-Approve; Part_Type: *LF_C1206
PC145 PC146 PC151 PC152 PC154 = CAP_NP_0: Lifecycle: Comp-Approve; Part_Type: *LF_C0402
PC147-PC150 = CAP_NP: Lifecycle: Comp-Approve; Part_Type: *LF_C0805
PC153 PC1446 = CAP_NP: Lifecycle: Comp-Approve; Part_Type: *LF_C0402
PC1444 PC1445 = CAP_NP: Lifecycle: Comp-Approve; Part_Type: *LF_C_POSCAP
PL20 PL21 = L: Lifecycle: Comp-Approve; Part_Type: *LF_Inductor
PR62 PR64-PR66 = R: Lifecycle: Comp-Approve; Part_Type: *LF_Resistor; WATTAGE: 1/16W
PR63 = R: Lifecycle: Comp-Approve; Not_insert: NI; Part_Type: *LF_Resistor; WATTAGE: 1/16W
PU10 = MPQ8633AGL: Lifecycle: P/N Release; Part_Type: *LF_Chipset

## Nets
GND: C891.2 C892.2 C893.2 C894.2 C895.2 C896.2 C1005.2 C1006.2 JP1.1 JP1.2 JP1.3 JP1.4 JP1.5 JP7.3 JP8.3 JP9.3 JP10.3 JP11.3 JP12.3 JP13.3 JP14.3 PC61.2 PC62.2 PC63.2 PC65.2 PC66.2 PC67.2 PC68.2 PC69.2 PC70.2 PC71.2 PC72.2 PC73.2 PC75.2 PC76.2 PC77.2 PC78.2 PC79.2 PC80.2 PC81.2 PC82.2 PC83.2 PC84.2 PC85.1 PC86.1 PC87.2 PC88.2 PC91.2 PC92.2 PC93.2 PC94.2 PC97.2 PC99.2 PC100.2 PC101.2 PC102.2 PC103.2 PC104.2 PC105.2 PC106.2 PC107.2 PC108.2 PC109.2 PC110.1 PC111.2 PC112.1 PC114.2 PC116.2 PC117.2 PC118.2 PC119.2 PC122.2 PC124.2 PC125.2 PC126.2 PC127.2 PC128.2 PC129.2 PC130.2 PC131.2 PC132.2 PC133.2 PC135.2 PC136.2 PC137.2 PC138.2 PC139.2 PC140.2 PC142.2 PC143.2 PC144.2 PC145.2 PC147.2 PC148.2 PC149.2 PC150.2 PC151.2 PC152.2 PC154.2 PC1441.2 PC1442.2 PC1443.1 PC1444.2 PC1445.2 PC1446.1 PJ7.2 PJ11.2 PQ16.S2 PQ17.S2 PQ18.S2 PQ19.S2 PR28.2 PR29.2 PR30.2 PR34.2 PR35.2 PR36.2 PR46.2 PR56.2 PR60.2 PR61.2 PR65.2 PR66.2 PU5.10(PGND_1) PU5.11(PGND_2) PU5.12(PGND_3) PU5.13(PGND_4) PU5.14(PGND_5) PU5.21(MODE) PU5.22(GND) PU5.27(GND_1) PU5.28(GND_2) PU5.TH PU6.10(PGND_1) PU6.11(PGND_2) PU6.12(PGND_3) PU6.13(PGND_4) PU6.14(PGND_5) PU6.21(MODE) PU6.22(GND) PU6.27(GND_1) PU6.28(GND_2) PU6.TH PU7.25(GND-TH) PU8.25(GND-TH) PU9.2(AGND) PU9.6(RGND) PU9.11_18(PGND) PU10.2(AGND) PU10.6(RGND) PU10.11_18(PGND) U7.7(GND) U20.7(GND) U101.S ; also on sheet 3 4 5 6 7 8 9 10 11 12 13 14 15 16 17 18 19 20 21 22 23 24 25 26 27 28 29 30 31 32 33 34 35 36 37 38 39 40 41 42 43 44 45 46 47 48 49 50 51 52 53 54 55 56 57 58 59
P0V9A_PLX1: PC135.1 PC136.1 PC137.1 PC138.1 PC139.1 PC141.2 PC1441.1 PC1442.1 PL19.2 PR59.2 ; also on sheet 12 14 51
P0V9A_PLX2: PC147.1 PC148.1 PC149.1 PC150.1 PC151.1 PC153.2 PC1444.1 PC1445.1 PL21.2 PR64.2 ; also on sheet 24 26 51
P0V9A_PLX2_EN: PJ13.1 PU10.8(EN)
P0V9D_PLX1: PC84.1 PC87.1 PC88.1 PC97.1 PC100.1 PC101.1 PC102.1 PC103.1 PC104.1 PC105.1 PJ5.2 PL13.2 PL14.2 ; also on sheet 12 14 51
P0V9D_PLX1_BT1: PC89.1 PU7.20(BOOT1)
P0V9D_PLX1_BT2: PC90.1 PU7.10(BOOT2)
P0V9D_PLX1_COMP: PC96.1 PR44.1 PU7.6(COMP)
P0V9D_PLX1_COMP_RC: PC98.1 PR44.2
P0V9D_PLX1_DIFF_R: PJ6.2 PR40.1 PR43.1
P0V9D_PLX1_FB: PC95.2 PC96.2 PC98.2 PR43.2 PU7.5(FB)
P0V9D_PLX1_FS: PR46.1 PU7.22(FS)
P0V9D_PLX1_ISEN1: PR38.1 PU7.17(ISEN1)
P0V9D_PLX1_ISEN2: PR39.1 PU7.13(ISEN2)
P0V9D_PLX1_SS: PC99.1 PU7.23(SS)
P0V9D_PLX1_VCC: PC85.2 PR37.2 PU7.3(VMON) PU7.8(VCC) PU7.24(REFTRK)
P0V9D_PLX1_VDIFF_RC: PC95.1 PR40.2
P0V9D_PLX1_VREG: PR45.1 PU7.7(VREG)
P0V9D_PLX1_VSENSE: PR41.2 PR42.1 PU7.2(VSEN+)
P0V9D_PLX2: PC109.1 PC111.1 PC114.1 PC122.1 PC125.1 PC126.1 PC127.1 PC128.1 PC129.1 PC130.1 PJ9.2 PL16.2 PL17.2 ; also on sheet 24 26 51
P0V9D_PLX2_BT1: PC113.1 PU8.20(BOOT1)
P0V9D_PLX2_BT2: PC115.1 PU8.10(BOOT2)
P0V9D_PLX2_COMP: PC121.1 PR54.1 PU8.6(COMP)
P0V9D_PLX2_COMP_RC: PC123.1 PR54.2
P0V9D_PLX2_DIFF_R: PJ10.2 PR50.1 PR53.1
P0V9D_PLX2_FB: PC120.2 PC121.2 PC123.2 PR53.2 PU8.5(FB)
P0V9D_PLX2_FS: PR56.1 PU8.22(FS)
P0V9D_PLX2_ISEN1: PR48.1 PU8.17(ISEN1)
P0V9D_PLX2_ISEN2: PR49.1 PU8.13(ISEN2)
P0V9D_PLX2_SS: PC124.1 PU8.23(SS)
P0V9D_PLX2_VCC: PC112.2 PR47.2 PU8.3(VMON) PU8.8(VCC) PU8.24(REFTRK)
P0V9D_PLX2_VDIFF_RC: PC120.1 PR50.2
P0V9D_PLX2_VREG: PR55.1 PU8.7(VREG)
P0V9D_PLX2_VSENSE: PR51.2 PR52.1 PU8.2(VSEN+)
P1V8A_PLX1: L9.2 ; also on sheet 9 12 14
P1V8A_PLX2: L10.2 ; also on sheet 21 24 26
P1V8D_PLX1: L9.1 PC65.1 PC66.1 PC67.1 PC68.1 PJ15.1 PL9.2 PU5.24(VO) ; also on sheet 9 10 11 12 14 46 51
P1V8D_PLX2: L10.1 PC75.1 PC76.1 PC77.1 PC78.1 PJ16.1 PL11.2 PU6.24(VO) ; also on sheet 21 22 23 24 26 46 51
P3V3: C893.1 C896.1 JP1.10 PR25.1 PR31.1 PR45.2 PR55.2 PR57.1 PR58.1 PR62.1 PR63.1 R858.1 R859.1 ; also on sheet 10 22 27 28 31 32 33 34 35 36 37 38 41 44 51 53 59
P3V3_STBY: C1005.1 C1006.1 R804.1 R805.1 R806.1 R807.1 R808.1 R809.1 R810.1 R811.1 R812.1 R813.1 R814.1 R815.1 R816.1 R817.1 R818.1 U7.14(VCC) U20.14(VCC) ; also on sheet 27 28 29 30 31 32 33 34 35 36 37 38 39 40 43 44 45 46 48 49 50 51 54 55 58
P5V: C892.1 C895.1 JP1.8 JP1.9 PC69.1 PC79.1 PC86.2 PC110.2 PR37.1 PR47.1 PU5.19(VDD) PU6.19(VDD) PU7.15(PVCC) PU8.15(PVCC) ; also on sheet 41 51 57 59
P12V: C891.1 C894.1 JP1.6 JP1.7 ; also on sheet 34 35 41 42 50 57 59
P12V_1: PL8.1 PL12.2 PL18.1 ; also on sheet 31 32 33 42 48 52
P12V_2: PL10.1 PL15.2 PL20.1 ; also on sheet 36 37 38 42 49 52
P12V_HSC_1_BUF_EN: R816.2 U7.2(OUT) ; also on sheet 48
P12V_HSC_2_BUF_EN: R817.2 U7.4(OUT) ; also on sheet 49
P12V_HSC_3_BUF_EN: R818.2 U7.6(OUT) ; also on sheet 50
FM_PWR_EN_N: U101.G ; also on sheet 41
GPU_THROTTLE_N: R808.2 R809.2 U7.9(IN) U7.11(IN) U7.13(IN) U20.1(IN) U20.3(IN) U20.5(IN) U20.9(IN) U20.11(IN) U20.13(IN) ; also on sheet 29 30
GPU_THROTTLE_SLOT0_N: R805.2 R1179.1 R1180.2 ; also on sheet 31
GPU_THROTTLE_SLOT0_N_JP7_R: JP7.1 R1179.2
GPU_THROTTLE_SLOT0_N_U7D_R: R1180.1 U7.8(OUT)
GPU_THROTTLE_SLOT1_N: R806.2 R1182.1 R1184.2 ; also on sheet 32
GPU_THROTTLE_SLOT1_N_JP8_R: JP8.1 R1182.2
GPU_THROTTLE_SLOT1_U7E_N_R: R1184.1 U7.10(OUT)
GPU_THROTTLE_SLOT2_N: R807.2 R1183.1 R1185.2 ; also on sheet 33
GPU_THROTTLE_SLOT2_N_JP9_R: JP9.1 R1183.2
GPU_THROTTLE_SLOT2_U7F_N_R: R1185.1 U7.12(OUT)
GPU_THROTTLE_SLOT3_N: R810.2 R1186.2 R1191.1 ; also on sheet 34
GPU_THROTTLE_SLOT3_N_JP10_R: JP10.1 R1191.2
GPU_THROTTLE_SLOT3_U20A_N_R: R1186.1 U20.2(OUT)
GPU_THROTTLE_SLOT4_N: R811.2 R1187.2 R1192.1 ; also on sheet 35
GPU_THROTTLE_SLOT4_N_JP11_R: JP11.1 R1192.2
GPU_THROTTLE_SLOT4_U20B_N_R: R1187.1 U20.4(OUT)
GPU_THROTTLE_SLOT5_N: R812.2 R1188.2 R1193.1 ; also on sheet 36
GPU_THROTTLE_SLOT5_N_JP12_R: JP12.1 R1193.2
GPU_THROTTLE_SLOT5_U20C_N_R: R1188.1 U20.6(OUT)
GPU_THROTTLE_SLOT6_N: R813.2 R1189.2 R1194.1 ; also on sheet 37
GPU_THROTTLE_SLOT6_N_JP13_R: JP13.1 R1194.2
GPU_THROTTLE_SLOT6_U20D_N_R: R1189.1 U20.8(OUT)
GPU_THROTTLE_SLOT7_N: R814.2 R1190.2 R1195.1 ; also on sheet 38
GPU_THROTTLE_SLOT7_N_JP14_R: JP14.1 R1195.2
GPU_THROTTLE_SLOT7_U20E_N_R: R1190.1 U20.10(OUT)
HOT_SWAP_EN: R804.2 R815.2 U7.1(IN) U7.3(IN) U7.5(IN) U101.D
NC_P1V8D_PLX_1_5: PU5.5(NC_1)
NC_P1V8D_PLX_1_18: PU5.18(NC_2)
NC_P1V8D_PLX_1_26: PU5.26(DNC)
NC_P1V8D_PLX_2_5: PU6.5(NC_1)
NC_P1V8D_PLX_2_18: PU6.18(NC_2)
NC_P1V8D_PLX_2_26: PU6.26(DNC)
PWRGD_P0V9A_PLX1: PR57.2 PU9.9(PG)
PWRGD_P0V9A_PLX2: PR62.2 PU10.9(PG)
PWRGD_P0V9D_PLX1: PU7.21(PGOOD) R858.2
PWRGD_P0V9D_PLX2: PU8.21(PGOOD) R859.2
PWRGD_P1V8D_PLX_1: PJ4.2 PJ12.2 PR25.2 PU5.2(PGOOD)
PWRGD_P1V8D_PLX_2: PJ8.2 PJ13.2 PR31.2 PU6.2(PGOOD)
PWRGD_P3V3: PJ2.2 PJ3.2 ; also on sheet 41 59
SH_P0V9A_PLX1_EN: PJ12.1 PU9.8(EN)
SH_P0V9D_PLX1_EN: PJ4.1 PU7.9(EN)
SH_P0V9D_PLX1_VDIFF: PJ6.1 PU7.4(VDIFF)
SH_P0V9D_PLX1_VSENSE_N: PJ7.1 PR42.2 PU7.1(VSEN-)
SH_P0V9D_PLX1_VSENSE_P: PJ5.1 PR41.1
SH_P0V9D_PLX2_EN: PJ8.1 PU8.9(EN)
SH_P0V9D_PLX2_VDIFF: PJ10.1 PU8.4(VDIFF)
SH_P0V9D_PLX2_VSENSE_N: PJ11.1 PR52.2 PU8.1(VSEN-)
SH_P0V9D_PLX2_VSENSE_P: PJ9.1 PR51.1
SH_P1V8D_PLX_1_EN: PJ2.1 PU5.3(EN)
SH_P1V8D_PLX_1_FB_P: PJ15.2 PR27.2
SH_P1V8D_PLX_2_EN: PJ3.1 PU6.3(EN)
SH_P1V8D_PLX_2_FB_P: PJ16.2 PR33.2
SW_P0V9A_0_BT: PC134.1 PU9.1(BST)
SW_P0V9A_0_CS: PR61.1 PU9.3(CS)
SW_P0V9A_0_FB: PC141.1 PR59.1 PR60.1 PU9.7(FB)
SW_P0V9A_0_FILT: PC131.1 PC132.1 PC133.1 PL18.2 PU9.10(VIN)
SW_P0V9A_0_SW: PC134.2 PL19.1 PU9.20(SW)
SW_P0V9A_0_TR: PC142.1 PC1443.2 PU9.5(TRK_REF)
SW_P0V9A_0_VCC: PC140.1 PR58.2 PU9.4(MODE) PU9.19(VCC)
SW_P0V9A_1_BT: PC146.1 PU10.1(BST)
SW_P0V9A_1_CS: PR66.1 PU10.3(CS)
SW_P0V9A_1_FB: PC153.1 PR64.1 PR65.1 PU10.7(FB)
SW_P0V9A_1_FILT: PC143.1 PC144.1 PC145.1 PL20.2 PU10.10(VIN)
SW_P0V9A_1_SW: PC146.2 PL21.1 PU10.20(SW)
SW_P0V9A_1_TR: PC154.1 PC1446.2 PU10.5(TRK_REF)
SW_P0V9A_1_VCC: PC152.1 PR63.2 PU10.4(MODE) PU10.19(VCC)
SW_P0V9D_PLX1_FLT: PC81.1 PC82.1 PC83.1 PC91.1 PC92.1 PC93.1 PC94.1 PL12.1 PQ16.D1(3,4) PQ17.D1(3,4)
SW_P0V9D_PLX1_LG1: PQ16.8(G2) PU7.16(LGATE1)
SW_P0V9D_PLX1_LG2: PQ17.8(G2) PU7.14(LGATE2)
SW_P0V9D_PLX1_PH1: PC89.2 PQ16.2(S1) PU7.18(PHASE1)
SW_P0V9D_PLX1_PH2: PC90.2 PQ17.2(S1) PU7.12(PHASE2)
SW_P0V9D_PLX1_SW1: PL13.1 PQ16.5(S1/D2-1) PQ16.6(S1/D2-2) PQ16.7(S1/D2-3) PR38.2
SW_P0V9D_PLX1_SW2: PL14.1 PQ17.5(S1/D2-1) PQ17.6(S1/D2-2) PQ17.7(S1/D2-3) PR39.2
SW_P0V9D_PLX1_UG1: PQ16.1(G1) PU7.19(UGATE1)
SW_P0V9D_PLX1_UG2: PQ17.1(G1) PU7.11(UGATE2)
SW_P0V9D_PLX2_FLT: PC106.1 PC107.1 PC108.1 PC116.1 PC117.1 PC118.1 PC119.1 PL15.1 PQ18.D1(3,4) PQ19.D1(3,4)
SW_P0V9D_PLX2_LG1: PQ18.8(G2) PU8.16(LGATE1)
SW_P0V9D_PLX2_LG2: PQ19.8(G2) PU8.14(LGATE2)
SW_P0V9D_PLX2_PH1: PC113.2 PQ18.2(S1) PU8.18(PHASE1)
SW_P0V9D_PLX2_PH2: PC115.2 PQ19.2(S1) PU8.12(PHASE2)
SW_P0V9D_PLX2_SW1: PL16.1 PQ18.5(S1/D2-1) PQ18.6(S1/D2-2) PQ18.7(S1/D2-3) PR48.2
SW_P0V9D_PLX2_SW2: PL17.1 PQ19.5(S1/D2-1) PQ19.6(S1/D2-2) PQ19.7(S1/D2-3) PR49.2
SW_P0V9D_PLX2_UG1: PQ18.1(G1) PU8.19(UGATE1)
SW_P0V9D_PLX2_UG2: PQ19.1(G1) PU8.11(UGATE2)
SW_P1V8D_PLX_1_BT: PC64.1 PU5.4(VBST)
SW_P1V8D_PLX_1_PH: PC64.2 PL9.1 PU5.6(SW_1) PU5.7(SW_2) PU5.8(SW_3) PU5.9(SW_4)
SW_P1V8D_PLX_2_BT: PC74.1 PU6.4(VBST)
SW_P1V8D_PLX_2_PH: PC74.2 PL11.1 PU6.6(SW_1) PU6.7(SW_2) PU6.8(SW_3) PU6.9(SW_4)
SW_P12V_P1V8D_PLX_1_FILT: PC61.1 PC62.1 PC63.1 PL8.2 PU5.15(VIN_1) PU5.16(VIN_2) PU5.17(VIN_3)
SW_P12V_P1V8D_PLX_2_FILT: PC71.1 PC72.1 PC73.1 PL10.2 PU6.15(VIN_1) PU6.16(VIN_2) PU6.17(VIN_3)
TP_GPU_THROTTLE_BUF_OD_RESERVE_1: U20.12(OUT)
VR_P1V8D_PLX_1_FB: PR27.1 PR29.1 PU5.23(FB)
VR_P1V8D_PLX_1_RF: PR26.2 PR28.1 PU5.1(RF)
VR_P1V8D_PLX_1_TRIP: PR30.1 PU5.25(TRIP)
VR_P1V8D_PLX_1_VREG: PC70.1 PR26.1 PU5.20(VREG)
VR_P1V8D_PLX_2_FB: PR33.1 PR35.1 PU6.23(FB)
VR_P1V8D_PLX_2_RF: PR32.2 PR34.1 PU6.1(RF)
VR_P1V8D_PLX_2_TRIP: PR36.1 PU6.25(TRIP)
VR_P1V8D_PLX_2_VREG: PC80.1 PR32.1 PU6.20(VREG)

Not connected (* = marked no-connect by the designer): JP7 2; JP8 2; JP9 2; JP10 2; JP11 2; JP12 2; JP13 2; JP14 2

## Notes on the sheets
sheet 62
- 6*6
- 6*6
sheet 63
- 6*6
- 6*6
